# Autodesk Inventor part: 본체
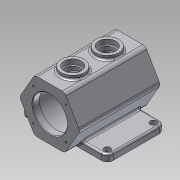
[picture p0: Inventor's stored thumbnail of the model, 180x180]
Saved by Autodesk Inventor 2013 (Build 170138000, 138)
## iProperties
Created: 2021-06
Part Number: 본체
Material: 알루미늄 6061
Document SubType Name: Modeling
Designer: hana-cad17
Density: 2.71 g/cm^3
Mass: 1500.83 g
Surface Area: 1102.36 cm^2
Volume: 553.812 cm^3
Author: hana-cad17
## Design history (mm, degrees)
sketch "스케치1" dims "d0" = 105
  geometry: L1 (26.25, 45.466)-(52.5, 0); L2 (52.5, 0)-(26.25, -45.466); L3 (26.25, -45.466)-(-26.25, -45.466); L4 (-26.25, -45.466)-(-52.5, 0); L5 (-52.5, 0)-(-26.25, 45.466); L6 (-26.25, 45.466)-(26.25, 45.466); L7 (73.5, 0)-(-73.5, 0) reference; L8 (0, -73.5)-(0, 73.5) reference; 3 further points
  constraints: 12 end point, 2 coincident, 1 horizontal alignment, 1 point on line, 15 other
extrude "돌출1" new body sketch "스케치1" stored distance "d2" = 140; taper "d3" = 0 deg
node "작업 평면1"
sketch "스케치2"
  geometry: L1 (-105, 0)-(105, 0) reference; L2 (0, -98)-(0, 98) reference; L3 (-75, 55)-(75, 55); L4 (75, 55)-(75, -45); L5 (75, -45)-(-75, -45); L6 (-75, -45)-(-75, 55); L7 (-75, 55)-(75, -45); L8 (75, 55)-(-75, -45); L9 (-26.25, -70)-(-26.25, 70) reference; L10 (-52.5, 70)-(-26.25, 70) reference; L11 (-52.5, 70)-(-52.5, -70) reference; L12 (-26.25, -70)-(-52.5, -70) reference; L13 (26.25, 70)-(26.25, -70) reference; L14 (-26.25, 70)-(26.25, 70) reference; L15 (-26.25, -70)-(-26.25, 70) reference; L16 (26.25, -70)-(-26.25, -70) reference; L17 (52.5, 70)-(52.5, -70) reference; L18 (26.25, 70)-(52.5, 70) reference; L19 (26.25, 70)-(26.25, -70) reference; L20 (52.5, -70)-(26.25, -70) reference; 2 further points
  constraints: 12 end point, 2 midpoint, 2 parallel, 1 horizontal, 1 perpendicular, 1 point on line
  dimensions: "d9" = 25 distance between parallel lines of L5 L16; "d10" = 100 distance of L5.end L3.start; "d11" = 150 distance of L3.start L3.end
extrude "돌출2" join sketch "스케치2" distance "d12" = 12; taper "d13" = 0 deg
fillet "모깎기1" dims "d14" = 10
sketch "스케치3"
  geometry: C1 r 5.5 at (-65, 45); C2 r 5.5 at (-65, -35); C3 r 5.5 at (65, -35); C4 r 5.5 at (65, 45); A1 r 10 centre (65, 45) between (75, 45) and (65, 55) reference; A2 r 10 centre (-65, 45) between (-65, 55) and (-75, 45) reference; A3 r 10 centre (-65, -35) between (-75, -35) and (-65, -45) reference; A4 r 10 centre (65, -35) between (65, -45) and (75, -35) reference; 1 further point
  constraints: 4 centre point, 4 coincident, 3 equal radius
  dimensions: "d15" = 11 diameter of C1
extrude "돌출3" cut sketch "스케치3" stored distance "d17" = 12; taper "d18" = 0 deg
sketch "스케치4"
  geometry: C1 r 30 at (0, 0); 1 further point
  constraints: 1 centre point, 1 coincident
  dimensions: "d19" = 60 diameter of C1
extrude "돌출4" cut sketch "스케치4" distance "d21" = 12; taper "d22" = 0 deg
sketch "스케치5"
  geometry: C1 r 30 at (0, 0) reference; C2 r 37.5 at (0, 0)
  constraints: 1 centre point, 1 coincident
  dimensions: "d23" = 75 diameter of C2
extrude "돌출5" cut sketch "스케치5" distance "d25" = 116; taper "d26" = 0 deg
sketch "스케치6"
  geometry: C1 r 37.5 at (0, 0) reference; C2 r 30 at (0, 0)
  constraints: 1 centre point, 1 coincident
  dimensions: "d27" = 60 diameter of C2
extrude "돌출6" cut sketch "스케치6" distance "d29" = 12; taper "d30" = 0 deg
node "작업 평면2"
sketch "스케치10"
  geometry: L1 (-105, 0)-(105, 0) reference; L2 (0, -98)-(0, 98) reference; L3 (-26.25, -45)-(26.25, -45) reference; L4 (26.25, 70)-(26.25, -70) reference; L5 (-26.25, 70)-(26.25, 70) reference; L6 (-26.25, -70)-(-26.25, 70) reference; L7 (26.25, -70)-(-26.25, -70) reference; C1 r 20 at (0, -30); C2 r 20 at (0, 30); 1 further point
  constraints: 2 centre point, 2 point on line
  dimensions: "d61" = 40 diameter of C1; "d63" = 40 diameter of C2; "d64" = 40 distance from line of L7 C1.centre; "d65" = 60 distance of C1.centre C2.centre
extrude "돌출7" join sketch "스케치10" stored distance "d66" = 11; taper "d67" = 0 deg
sketch "스케치11"
  geometry: C1 r 20 at (0, 0) reference; C2 r 15 at (0, 0); C3 r 20 at (0, 60) reference; C4 r 15 at (0, 60); 1 further point
  constraints: 2 centre point, 2 coincident
  dimensions: "d68" = 30 diameter of C2; "d70" = 30 diameter of C4
extrude "돌출8" cut sketch "스케치11" distance "d71" = 8; taper "d72" = 0 deg
sketch "스케치12"
  geometry: C1 r 15 at (0, 0) reference; C2 r 15 at (0, 60) reference; C3 r 12.5 at (0, 0); C4 r 12.5 at (0, 60); 1 further point
  constraints: 2 centre point, 2 coincident
  dimensions: "d73" = 25 diameter of C3; "d75" = 25 diameter of C4
extrude "돌출9" cut sketch "스케치12" stored distance "d76" = 0; taper "d77" = 0 deg
sketch "스케치13"
  geometry: L1 (-105, 0)-(105, 0) reference; L2 (0, -70.5)-(0, 73) reference; L3 (0, 0)-(-59.378, 59.378); L4 (0, 0)-(50.749, 50.749); L5 (0, 0)-(-77.756, -77.756); L6 (0, 0)-(69.454, -69.454); C1 r 30 at (0, 0) reference; A1 r 40 centre (0, 0) between (-28.284, 28.284) and (28.284, 28.284); 2 further points
  constraints: 8 end point, 4 point on circle, 4 point on line, 1 centre point, 1 coincident
  dimensions: "d78" = 80 diameter of A1; "d80" = 45 deg angle of L2 L3; "d82" = 45 deg angle of L2 L5; "d84" = 45 deg angle of L2 L6; "d86" = 45 deg angle of L4 L2
hole "구멍3" sketch "스케치13" at (-28.284, 28.284), (28.284, 28.284), (28.284, -28.284), (-28.284, -28.284) diameter "d88" = 3.242; stored, may be unused: countersink angle "d92" = 90 deg, drill point angle "d94" = 118 deg; dims "d89" = 8, "d90" = 4, "d91" = 2, "d93" = 10
fillet "모깎기2" dims "d95" = 8, "d96" = 3, "d113" = 5
chamfer "모따기1" distance "d97" = 1; stored, may be unused: second distance "d98" = 2, angle "d99" = 45 deg
sketch "스케치14"
  geometry: L1 (-75, 45)-(-75, -35) reference; L2 (-65, -45)-(-32.293, -45) reference; 2 further points
  constraints: 1 other
  dimensions: "d100" = 14 distance from line of point (-61, 5) L1; "d101" = 50 distance from line of L2 point (-61, 5)
feature "엠보싱1" sketch "스케치14" dims "d0" = 105, "d102" = 0.5, "d103" = 0
sketch "스케치15"
  geometry: L1 (-105, 0)-(105, 0) reference; L2 (0, 70.5)-(0, -73) reference; C1 r 31 at (0, 0) reference; A1 r 40 centre (0, 0) between (0, -40) and (40, 0); 2 further points
  constraints: 4 point on circle, 4 point on line, 1 centre point, 1 coincident
  dimensions: "d104" = 80 diameter of A1
hole "구멍4" sketch "스케치15" at (0, -40), (40, 0), (0, 40), (-40, 0) diameter "d106" = 3.242; stored, may be unused: countersink angle "d110" = 90 deg, drill point angle "d112" = 118 deg; dims "d107" = 8, "d108" = 4, "d109" = 2, "d111" = 10
node "솔리드1"
node "투영된 루프3"
node "투영된 루프4"
node "투영된 루프5"
node "투영된 루프7"
node "투영된 루프8"
node "투영된 루프9"
other parameters: "d60" = 52.5
